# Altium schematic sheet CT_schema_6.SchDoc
size 479 x 328 mm
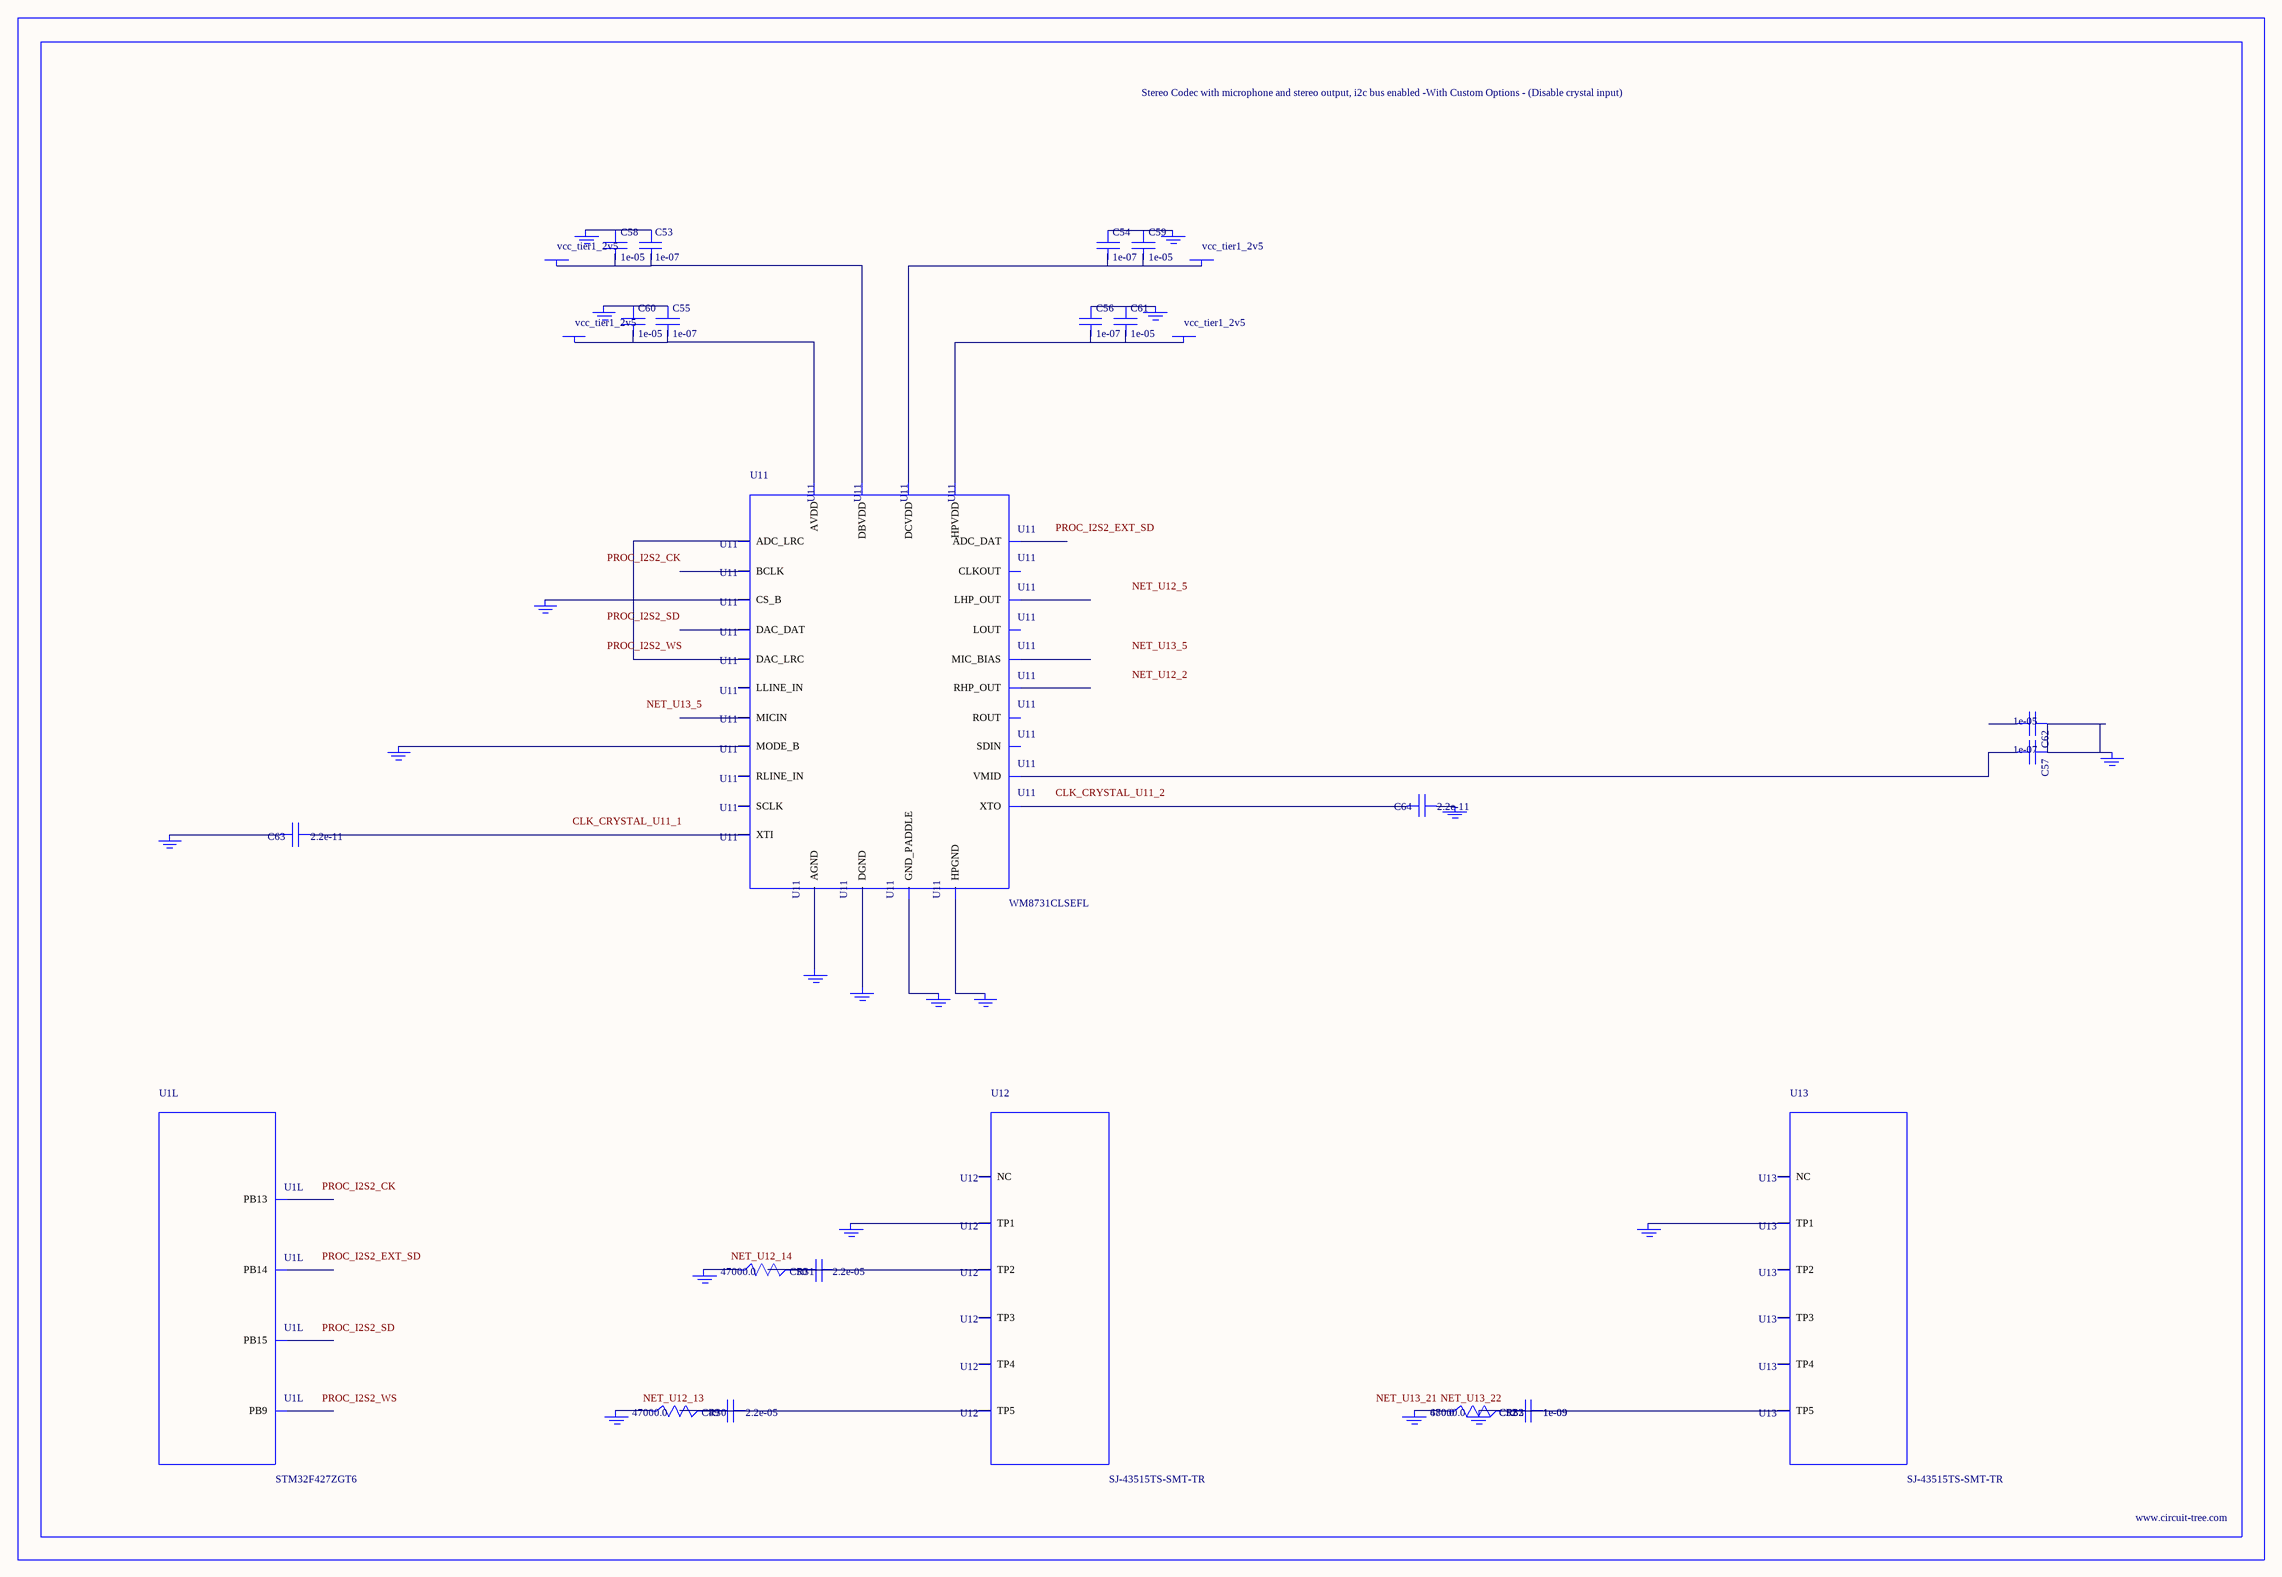
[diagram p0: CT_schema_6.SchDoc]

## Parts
BORDER5  (no value)
C49  2.2e-05  [C1210]
C50  2.2e-05  [C1210]
C51  1e-09  [C0402]
C52  1e-09  [C0402]
C53  1e-07  [C0402]
C54  1e-07  [C0402]
C55  1e-07  [C0402]
C56  1e-07  [C0402]
C57  1e-07  [C0402]
C58  1e-05  [C0805]
C59  1e-05  [C0805]
C60  1e-05  [C0805]
C61  1e-05  [C0805]
C62  1e-05  [C0805]
C63  2.2e-11  [C0402]
C64  2.2e-11  [C0402]
GND_INSTANCE_5_0  (no value)
GND_INSTANCE_5_1  (no value)
GND_INSTANCE_5_2  (no value)
GND_INSTANCE_5_3  (no value)
GND_INSTANCE_5_4  (no value)
GND_INSTANCE_5_5  (no value)
GND_INSTANCE_5_6  (no value)
GND_INSTANCE_5_7  (no value)
GND_INSTANCE_5_8  (no value)
GND_INSTANCE_5_9  (no value)
GND_INSTANCE_5_10  (no value)
GND_INSTANCE_5_11  (no value)
GND_INSTANCE_5_12  (no value)
GND_INSTANCE_5_13  (no value)
GND_INSTANCE_5_14  (no value)
GND_INSTANCE_5_15  (no value)
GND_INSTANCE_5_16  (no value)
GND_INSTANCE_5_17  (no value)
GND_INSTANCE_5_18  (no value)
POWER_INSTANCE_5_0  vcc_tier1_2v5
POWER_INSTANCE_5_1  vcc_tier1_2v5
POWER_INSTANCE_5_2  vcc_tier1_2v5
POWER_INSTANCE_5_3  vcc_tier1_2v5
R30  47000.0  [R0603]
R31  47000.0  [R0603]
R32  47000.0  [R0603]
R33  680.0  [R0603]
U1  STM32F427ZGT6  [LQFP144]  (part L of 12)
U11  WM8731CLSEFL  [QFN-28]
U12  SJ-43515TS-SMT-TR  [SJ-43515TS-SMT-TR]
U13  SJ-43515TS-SMT-TR  [SJ-43515TS-SMT-TR]

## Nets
NetC49_1: C49.1 C49.2 R30.2 U12.5(TP5)
NetC50_1: C50.1 C50.2 R31.2 U12.2(TP2)
NetC51_1: C51.1 C51.2 C52.1 C52.2 GND_INSTANCE_5_18.0(GND) R32.2 R33.2 U13.5(TP5)
NetC53_1: C53.1 C58.1 GND_INSTANCE_5_3.0(GND)
NetC53_2: C53.2 C58.2 POWER_INSTANCE_5_1.0(PWR) U11.5(DBVDD)
NetC54_1: C54.1 C59.1 GND_INSTANCE_5_2.0(GND)
NetC54_2: C54.2 C59.2 POWER_INSTANCE_5_0.0(PWR) U11.3(DCVDD)
NetC55_1: C55.1 C60.1 GND_INSTANCE_5_6.0(GND)
NetC55_2: C55.2 C60.2 POWER_INSTANCE_5_3.0(PWR) U11.18(AVDD)
NetC56_1: C56.1 C61.1 GND_INSTANCE_5_4.0(GND)
NetC56_2: C56.2 C61.2 POWER_INSTANCE_5_2.0(PWR) U11.12(HPVDD)
NetC57_1: C57.1 C62.1 GND_INSTANCE_5_7.0(GND)
NetC57_2: C57.2 U11.20(VMID)
NetC63_1: C63.1 U11.1(XTI)
NetC63_2: C63.2 GND_INSTANCE_5_0.0(GND)
NetC64_1: C64.1 GND_INSTANCE_5_1.0(GND)
NetC64_2: C64.2 U11.2(XTO)
NetGND_INSTANCE_5_5_0: GND_INSTANCE_5_5.0(GND) U11.15(HPGND)
NetGND_INSTANCE_5_8_0: GND_INSTANCE_5_8.0(GND) U11.25(MODE_B)
NetGND_INSTANCE_5_9_0: GND_INSTANCE_5_9.0(GND) U11.26(CS_B)
NetGND_INSTANCE_5_10_0: GND_INSTANCE_5_10.0(GND) U11.29(GND_PADDLE)
NetGND_INSTANCE_5_11_0: GND_INSTANCE_5_11.0(GND) U11.4(DGND)
NetGND_INSTANCE_5_12_0: GND_INSTANCE_5_12.0(GND) U11.19(AGND)
NetGND_INSTANCE_5_13_0: GND_INSTANCE_5_13.0(GND) U12.1(TP1)
NetGND_INSTANCE_5_14_0: GND_INSTANCE_5_14.0(GND) R31.1
NetGND_INSTANCE_5_15_0: GND_INSTANCE_5_15.0(GND) R30.1
NetGND_INSTANCE_5_16_0: GND_INSTANCE_5_16.0(GND) U13.1(TP1)
NetGND_INSTANCE_5_17_0: GND_INSTANCE_5_17.0(GND) R32.1 R33.1
NetU11_9: U11.9(DAC_LRC) U11.11(ADC_LRC)

Not connected (* = marked no-connect by the designer): C62 2; U1 74(PB13) 75(PB14) 76(PB15) 140(PB9); U11 6(CLKOUT) 7(BCLK) 8(DAC_DAT) 10(ADC_DAT) 13(LHP_OUT) 14(RHP_OUT) 16(LOUT) 17(ROUT) 21(MIC_BIAS) 22(MICIN) 23(RLINE_IN) 24(LLINE_IN) 27(SDIN) 28(SCLK); U12 3(TP3) 4(TP4) 6(NC); U13 2(TP2) 3(TP3) 4(TP4) 6(NC)

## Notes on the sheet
- Labels drawn without touching a wire or pin: CLK_CRYSTAL_U11_1, CLK_CRYSTAL_U11_2, NET_U12_2, NET_U12_5, NET_U12_13, NET_U12_14, NET_U13_5, NET_U13_21, NET_U13_22, PROC_I2S2_CK, PROC_I2S2_EXT_SD, PROC_I2S2_SD, PROC_I2S2_WS

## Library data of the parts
BORDER5 = BORDER_PAGE5
C49 C50 = C1210C224K5RACTU
C51 C52 = C0402C102K3RAC
C53-C57 = C0402C104K3RACTU
C58-C62 = C0805C106K8RACTU
C63 C64 = C0402C220K3RAC
GND_INSTANCE_5_0-GND_INSTANCE_5_18 = GND
POWER_INSTANCE_5_0-POWER_INSTANCE_5_3 = PWR
R30-R32 = RC0603JR-0747KL
R33 = RC0603JR-07680RL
